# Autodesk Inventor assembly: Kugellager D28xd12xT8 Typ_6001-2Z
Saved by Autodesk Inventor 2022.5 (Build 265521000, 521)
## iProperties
Created: 2024-12
Part Number: Kugellager D28xd12xT8 Typ_6001-2Z
Document SubType Name: Assembly
Designer: AdminForWorker
Title: Kugellager D28xd12xT8 Typ_6001-2Z v1
Author: AdminForWorker
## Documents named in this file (5)
- c:\worker\convert-fusion-r05-cosv3\tmp\job-1\332\temp\files\099a3570-5e2e-4882-a741-729b561b50ae\504472bd-2afe-4d5e-8b6b-1cd6607e0bac.zip.iam
- c:\worker\convert-fusion-r05-cosv3\tmp\job-1\332\temp\files\099a3570-5e2e-4882-a741-729b561b50ae\6001-2Z_InnerRing.ipt
- c:\worker\convert-fusion-r05-cosv3\tmp\job-1\332\temp\files\099a3570-5e2e-4882-a741-729b561b50ae\6001-2Z_Ball.ipt
- c:\worker\convert-fusion-r05-cosv3\tmp\job-1\332\temp\files\099a3570-5e2e-4882-a741-729b561b50ae\6001-2Z_OuterRing.ipt
- c:\worker\convert-fusion-r05-cosv3\tmp\job-1\332\temp\files\099a3570-5e2e-4882-a741-729b561b50ae\6001-2Z_Shield.ipt
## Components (14 placed, 4 different names)
1. 6001-2Z_InnerRing:1
2. 6001-2Z_Ball:1
3. 6001-2Z_Ball:2
4. 6001-2Z_Ball:3
5. 6001-2Z_Ball:4
6. 6001-2Z_Ball:5
7. 6001-2Z_Ball:6
8. 6001-2Z_Ball:7
9. 6001-2Z_Ball:8
10. 6001-2Z_Ball:9
11. 6001-2Z_Ball:10
12. 6001-2Z_OuterRing:1
13. 6001-2Z_Shield:1
14. 6001-2Z_Shield:2
